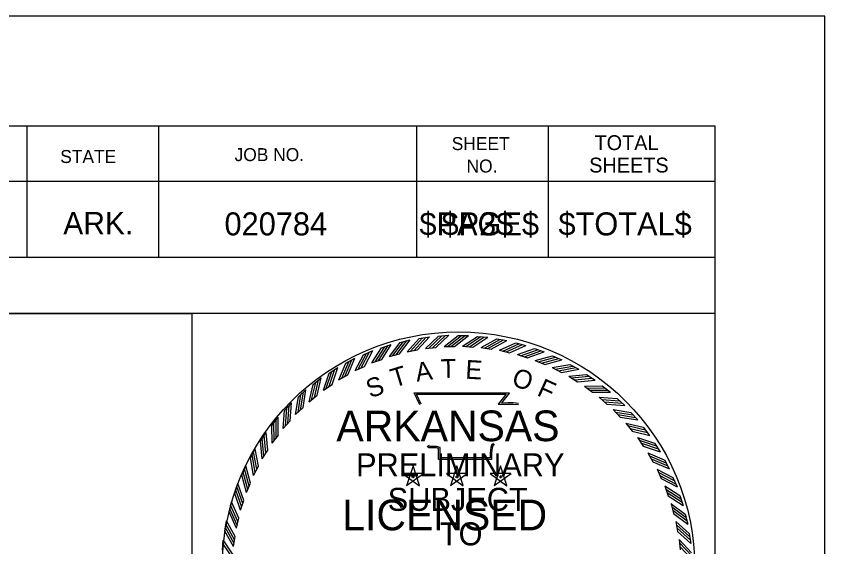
# Model space of a CAD drawing. Extents: x 0 to 1228743, y 0 to 152440.
# Drawn here: x 29.741 to 34, y 19.207 to 22 of the extents above; entities that cross this region are included whole.
import ezdxf

# ---------------------------------------------------------------- set-up
doc = ezdxf.new("R2010")
doc.units = 0
for name, color, linetype in [('R_Border', 7, 'Continuous'), ('R_Draft', 7, 'Continuous'), ('R_No Plot', 7, 'Continuous'), ('R_P1_To_Summary', 7, 'Continuous'), ('R_P2_Summary_To_End_PP', 7, 'Continuous'), ('R_P3_Cross_Sections', 7, 'Continuous'), ('STAMP_JUSTIN', 7, 'Continuous')]:
    doc.layers.add(name, color=color, linetype=linetype)

msp = doc.modelspace()

# ---------------------------------------------------------------- linework, layer by layer
at = {"layer": 'R_Border'}
for p, q in [((1.516, 21.4232), (33.4232, 21.4232)), ((29.7972, 21.4232), (29.7972, 20.7292)), ((30.4912, 21.4232), (30.4912, 20.7292)), ((31.8492, 21.4232), (31.8492, 20.7292)), ((32.5432, 21.4232), (32.5432, 20.7292)), ((33.4232, 0.5768), (33.4232, 21.4232)), ((33.4232, 21.1292), (29.1132, 21.1292)), ((33.4232, 21.1312), (33.4232, 21.1312)), ((33.4232, 20.7292), (29.1132, 20.7292)), ((33.4232, 20.4352), (27.1592, 20.4352))]:
    msp.add_line(p, q, dxfattribs=at)
msp.add_lwpolyline([(34, 22), (0, 22), (0, 0), (34, 0)], close=True, dxfattribs=at)
at = {"layer": 'R_Draft'}
msp.add_circle((32.0709, 19.0937), 1.2447, dxfattribs=at)
at = {"layer": 'R_No Plot'}
for points in [[(33.4232, 17.5816), (33.4232, 10.8708), (1.516, 10.8708), (1.516, 21.4232), (25.1972, 21.4232), (27.1592, 21.4232), (27.1592, 20.4352), (28.7492, 20.4352), (30.6666, 20.4352)], [(30.6666, 20.4352), (30.6666, 17.5816), (33.4232, 17.5816)]]:
    msp.add_lwpolyline(points, dxfattribs=at)
at = {"layer": 'STAMP_JUSTIN'}
for p, q in [((31.9657, 20.3158), (32.0198, 20.3208)), ((32.0686, 20.3188), (32.123, 20.3188)), ((31.7637, 20.2831), (31.8162, 20.297)), ((31.864, 20.3036), (31.9175, 20.3131)), ((32.1704, 20.3148), (32.2246, 20.3108)), ((32.272, 20.3016), (32.3257, 20.2931)), ((32.3721, 20.28), (32.4249, 20.2672)), ((31.5697, 20.2177), (31.6193, 20.2399)), ((31.6653, 20.2544), (31.7166, 20.2725)), ((31.801, 20.2338), (31.8547, 20.2433)), ((31.8972, 20.2514), (31.9514, 20.2564)), ((31.9945, 20.261), (32.0489, 20.261)), ((32.0922, 20.2625), (32.1465, 20.2585)), ((32.1897, 20.256), (32.2435, 20.2475)), ((32.2864, 20.2414), (32.3393, 20.2285)), ((32.4701, 20.2503), (32.5217, 20.2331)), ((31.4775, 20.1731), (31.525, 20.1994)), ((31.6147, 20.1752), (31.6661, 20.1933)), ((31.7067, 20.2084), (31.7593, 20.2222)), ((32.3815, 20.2189), (32.4332, 20.2017)), ((32.4745, 20.1886), (32.5245, 20.1672)), ((32.5654, 20.2126), (32.6153, 20.1912)), ((31.3892, 20.1212), (31.4344, 20.1513)), ((31.5258, 20.1345), (31.5755, 20.1569)), ((32.5646, 20.1507), (32.6127, 20.1252)), ((32.6572, 20.1671), (32.7052, 20.1417)), ((31.4406, 20.0867), (31.4882, 20.113)), ((32.6513, 20.1055), (32.6971, 20.0762)), ((32.7449, 20.1142), (32.7906, 20.0849)), ((31.3056, 20.0621), (31.3481, 20.0958)), ((31.3596, 20.0319), (31.4049, 20.0621)), ((31.2271, 19.9963), (31.2667, 20.0334)), ((32.7339, 20.0534), (32.7772, 20.0203)), ((32.8279, 20.0543), (32.8711, 20.0213)), ((31.2834, 19.9707), (31.3261, 20.0045)), ((32.812, 19.9945), (32.8524, 19.958)), ((32.9058, 19.9877), (32.9461, 19.9513)), ((31.1543, 19.9242), (31.1907, 19.9645)), ((31.2125, 19.9034), (31.2522, 19.9406)), ((32.8849, 19.9294), (32.9222, 19.8897)), ((32.9778, 19.9149), (33.015, 19.8753)), ((31.0877, 19.8464), (31.1206, 19.8896)), ((31.1474, 19.8304), (31.184, 19.8708)), ((32.9522, 19.8586), (32.9861, 19.8159)), ((31.0277, 19.7633), (31.057, 19.8091)), ((33.0436, 19.8364), (33.0774, 19.7938)), ((31.0886, 19.7524), (31.1217, 19.7956)), ((33.0135, 19.7824), (33.0437, 19.7371)), ((30.9748, 19.6756), (31.0003, 19.7236)), ((33.1027, 19.7527), (33.1329, 19.7075)), ((31.0364, 19.6697), (31.0658, 19.7156)), ((33.0682, 19.7014), (33.0946, 19.6537)), ((33.1547, 19.6645), (33.181, 19.6169)), ((30.9294, 19.5838), (30.9507, 19.6338)), ((30.9912, 19.583), (31.0167, 19.6312)), ((31.886, 19.5934), (31.7763, 19.5935)), ((31.7764, 19.5934), (31.865, 19.5288)), ((31.8312, 19.6332), (31.7972, 19.5289)), ((31.7973, 19.529), (31.8861, 19.5934)), ((31.865, 19.529), (31.8312, 19.6333)), ((32.1165, 19.5934), (32.0068, 19.5935)), ((32.0069, 19.5934), (32.0955, 19.5288)), ((32.0617, 19.6332), (32.0277, 19.5289)), ((32.0278, 19.529), (32.1166, 19.5934)), ((32.0955, 19.529), (32.0617, 19.6333)), ((32.3469, 19.5934), (32.2372, 19.5935)), ((32.2373, 19.5934), (32.326, 19.5288)), ((32.2921, 19.6332), (32.2581, 19.5289)), ((32.2583, 19.529), (32.3471, 19.5934)), ((32.326, 19.529), (32.2922, 19.6333)), ((33.1161, 19.6161), (33.1384, 19.5665)), ((31.8234, 19.5759), (31.8397, 19.5759)), ((31.8313, 19.5817), (31.8313, 19.568)), ((32.0538, 19.5759), (32.0701, 19.5759)), ((32.0618, 19.5817), (32.0618, 19.568)), ((32.2843, 19.5759), (32.3006, 19.5759)), ((32.2922, 19.5817), (32.2922, 19.568)), ((33.1992, 19.5722), (33.2215, 19.5227)), ((30.8917, 19.4886), (30.9088, 19.5401)), ((30.9534, 19.4929), (30.9748, 19.543)), ((33.1567, 19.5273), (33.1749, 19.4759)), ((33.236, 19.4766), (33.2541, 19.4254)), ((30.8619, 19.3906), (30.8748, 19.4434)), ((30.9231, 19.4), (30.9403, 19.4516)), ((33.1899, 19.4353), (33.2038, 19.3826)), ((30.8404, 19.2904), (30.8488, 19.3441)), ((30.9006, 19.3048), (30.9135, 19.3578)), ((33.2154, 19.3409), (33.2248, 19.2873)), ((33.2647, 19.3783), (33.2785, 19.3258)), ((30.886, 19.2082), (30.8945, 19.262)), ((33.2852, 19.2779), (33.2946, 19.2244)), ((30.8272, 19.1888), (30.8312, 19.243)), ((33.233, 19.2448), (33.238, 19.1905))]:
    msp.add_line(p, q, dxfattribs=at)
for points in [[(31.9146, 20.2528), (31.9831, 20.3172)], [(31.9333, 20.2549), (32.0018, 20.3193)], [(31.9514, 20.2564), (32.0199, 20.3208)], [(31.9944, 20.261), (32.0685, 20.3188)], [(32.0119, 20.2608), (32.086, 20.3186)], [(32.0308, 20.2612), (32.1049, 20.319)], [(32.0489, 20.261), (32.123, 20.3189)], [(31.7066, 20.2083), (31.7636, 20.2831)], [(31.7236, 20.2126), (31.7805, 20.2874)], [(31.7417, 20.2178), (31.7987, 20.2926)], [(31.7593, 20.2222), (31.8162, 20.297)], [(31.801, 20.2338), (31.8639, 20.3036)], [(31.8182, 20.2366), (31.8812, 20.3065)], [(31.8367, 20.2403), (31.8997, 20.3101)], [(31.8546, 20.2433), (31.9176, 20.3131)], [(31.8971, 20.2514), (31.9656, 20.3157)], [(32.0921, 20.2625), (32.1703, 20.3147)], [(32.1096, 20.261), (32.1877, 20.3133)], [(32.1284, 20.2601), (32.2066, 20.3123)], [(32.1465, 20.2586), (32.2246, 20.3108)], [(32.1897, 20.2559), (32.2719, 20.3015)], [(32.2069, 20.2531), (32.2891, 20.2986)], [(32.2256, 20.2505), (32.3079, 20.2961)], [(32.2435, 20.2476), (32.3257, 20.2931)], [(32.2863, 20.2414), (32.372, 20.28)], [(32.3033, 20.2371), (32.389, 20.2757)], [(31.5588, 20.1496), (31.6027, 20.2327)], [(31.5754, 20.1569), (31.6193, 20.24)], [(31.6147, 20.1751), (31.6653, 20.2543)], [(31.6312, 20.1808), (31.6818, 20.26)], [(31.6489, 20.1875), (31.6995, 20.2667)], [(31.666, 20.1933), (31.7166, 20.2726)], [(32.3217, 20.233), (32.4074, 20.2716)], [(32.3393, 20.2286), (32.425, 20.2672)], [(32.3814, 20.2188), (32.47, 20.2503)], [(32.398, 20.2132), (32.4866, 20.2446)], [(32.416, 20.2076), (32.5046, 20.239)], [(32.4331, 20.2017), (32.5218, 20.2332)], [(31.4722, 20.1044), (31.5091, 20.1909)], [(31.4882, 20.113), (31.525, 20.1995)], [(31.5258, 20.1344), (31.5697, 20.2176)], [(31.5418, 20.1415), (31.5857, 20.2246)], [(32.4744, 20.1886), (32.5653, 20.2126)], [(32.4904, 20.1815), (32.5813, 20.2055)], [(32.5079, 20.1745), (32.5988, 20.1985)], [(32.5245, 20.1672), (32.6154, 20.1912)], [(31.4048, 20.0621), (31.4345, 20.1514)], [(31.4405, 20.0866), (31.4774, 20.1731)], [(31.4559, 20.0949), (31.4928, 20.1814)], [(32.5645, 20.1507), (32.6571, 20.1671)], [(32.5799, 20.1424), (32.6725, 20.1588)], [(32.5968, 20.1339), (32.6893, 20.1503)], [(31.3596, 20.0318), (31.3892, 20.1211)], [(31.3742, 20.0414), (31.4038, 20.1306)], [(31.3897, 20.0522), (31.4193, 20.1415)], [(32.6127, 20.1253), (32.7052, 20.1417)], [(32.6512, 20.1055), (32.7448, 20.1142)], [(32.6658, 20.096), (32.7594, 20.1047)], [(31.2834, 19.9706), (31.3055, 20.062)], [(31.2972, 19.9813), (31.3193, 20.0727)], [(31.3117, 19.9934), (31.3339, 20.0848)], [(31.326, 20.0045), (31.3481, 20.0959)], [(32.6819, 20.0861), (32.7756, 20.0949)], [(32.6971, 20.0762), (32.7907, 20.085)], [(31.2389, 19.9283), (31.2534, 20.0212)], [(31.2522, 19.9406), (31.2667, 20.0335)], [(31.8662, 19.9551), (31.8372, 20.0179), (32.3384, 20.0182), (32.2965, 19.9656), (32.3305, 19.966), (32.359, 19.9664), (32.3874, 19.9633)], [(32.7338, 20.0534), (32.8279, 20.0543)], [(32.7476, 20.0426), (32.8417, 20.0436)], [(32.7629, 20.0315), (32.8569, 20.0324)], [(32.7772, 20.0204), (32.8712, 20.0213)], [(31.2125, 19.9033), (31.227, 19.9962)], [(31.2254, 19.9151), (31.2399, 20.008)], [(31.8734, 19.9585), (31.8496, 20.0099), (32.3219, 20.0102), (32.2798, 19.9574), (32.3306, 19.9581), (32.3586, 19.9584), (32.3865, 19.9554)], [(32.8119, 19.9945), (32.9057, 19.9877)], [(32.8248, 19.9827), (32.9185, 19.9759)], [(31.1593, 19.8432), (31.1661, 19.937)], [(31.1716, 19.8575), (31.1784, 19.9513)], [(31.1839, 19.8708), (31.1907, 19.9646)], [(32.8391, 19.9703), (32.9328, 19.9635)], [(32.8524, 19.9581), (32.9461, 19.9513)], [(31.1474, 19.8303), (31.1542, 19.9241)], [(32.8848, 19.9295), (32.9777, 19.9149)], [(32.8967, 19.9166), (32.9896, 19.9021)], [(32.9099, 19.9031), (33.0028, 19.8886)], [(31.0993, 19.7661), (31.0984, 19.8601)], [(31.1105, 19.7813), (31.1095, 19.8754)], [(31.1216, 19.7956), (31.1206, 19.8896)], [(32.9222, 19.8898), (33.0151, 19.8753)], [(32.9522, 19.8586), (33.0435, 19.8364)], [(31.0657, 19.7155), (31.057, 19.8092)], [(31.0886, 19.7523), (31.0876, 19.8463)], [(32.9629, 19.8448), (33.0543, 19.8226)], [(32.975, 19.8303), (33.0663, 19.8081)], [(32.9861, 19.816), (33.0775, 19.7938)], [(31.0364, 19.6696), (31.0277, 19.7632)], [(31.046, 19.6843), (31.0373, 19.7779)], [(31.0558, 19.7004), (31.0471, 19.794)], [(33.0134, 19.7824), (33.1026, 19.7528)], [(33.023, 19.7678), (33.1122, 19.7381)], [(31.0167, 19.6311), (31.0002, 19.7237)], [(32.2594, 19.7451), (32.2508, 19.7382), (32.248, 19.7278), (32.2452, 19.7018), (32.2452, 19.6672), (31.9654, 19.6672), (31.9654, 19.7139), (31.9654, 19.7243), (31.9541, 19.7278), (31.9143, 19.7278), (31.9072, 19.7386)], [(32.2544, 19.7513), (32.2438, 19.7427), (32.2402, 19.7293), (32.2372, 19.7022), (32.2372, 19.6751), (31.9733, 19.6751), (31.9733, 19.7139), (31.9733, 19.7302), (31.9552, 19.7357), (31.9185, 19.7357), (31.9138, 19.7429)], [(33.0338, 19.7523), (33.123, 19.7227)], [(33.0437, 19.7371), (33.1329, 19.7075)], [(30.9996, 19.5983), (30.9832, 19.6909)], [(31.008, 19.6152), (30.9916, 19.7078)], [(33.0681, 19.7014), (33.1546, 19.6645)], [(33.0765, 19.686), (33.1629, 19.6491)], [(30.9913, 19.5829), (30.9748, 19.6755)], [(33.086, 19.6697), (33.1724, 19.6328)], [(33.0946, 19.6538), (33.1811, 19.6169)], [(30.9604, 19.5088), (30.9364, 19.5997)], [(30.9675, 19.5264), (30.9435, 19.6173)], [(30.9747, 19.5429), (30.9507, 19.6338)], [(33.116, 19.6162), (33.1991, 19.5723)], [(33.123, 19.6002), (33.2062, 19.5563)], [(30.9534, 19.4928), (30.9294, 19.5837)], [(33.1311, 19.5831), (33.2143, 19.5392)], [(33.1384, 19.5665), (33.2216, 19.5226)], [(30.9344, 19.4345), (30.9029, 19.5231)], [(30.9402, 19.4516), (30.9088, 19.5402)], [(33.1567, 19.5273), (33.2359, 19.4767)], [(33.1623, 19.5108), (33.2416, 19.4601)], [(30.9231, 19.3999), (30.8917, 19.4885)], [(30.9288, 19.4164), (30.8974, 19.505)], [(33.169, 19.4931), (33.2483, 19.4425)], [(33.1749, 19.476), (33.2541, 19.4254)], [(30.909, 19.3402), (30.8703, 19.4259)], [(30.9134, 19.3577), (30.8748, 19.4434)], [(33.1898, 19.4354), (33.2646, 19.3784)], [(30.9006, 19.3048), (30.862, 19.3905)], [(30.9049, 19.3217), (30.8663, 19.4074)], [(33.1941, 19.4184), (33.2689, 19.3614)], [(33.1993, 19.4003), (33.2741, 19.3433)], [(33.2038, 19.3827), (33.2786, 19.3257)], [(30.8944, 19.2619), (30.8488, 19.3442)], [(33.2153, 19.341), (33.2851, 19.278)], [(30.8889, 19.2254), (30.8433, 19.3076)], [(30.8914, 19.2441), (30.8458, 19.3263)], [(33.2182, 19.3237), (33.288, 19.2608)], [(33.2219, 19.3052), (33.2917, 19.2422)], [(30.886, 19.2081), (30.8404, 19.2903)], [(33.2249, 19.2874), (33.2947, 19.2244)], [(30.8819, 19.1469), (30.8297, 19.225)], [(30.8834, 19.1649), (30.8312, 19.2431)], [(33.2329, 19.2448), (33.2973, 19.1763)], [(33.2344, 19.2274), (33.2987, 19.1589)], [(33.2365, 19.2086), (33.3009, 19.1401)]]:
    msp.add_lwpolyline(points, dxfattribs=at)

# ---------------------------------------------------------------- texts
at = {"layer": 'R_Border'}
for s, height, p in [('SHEET', 0.0684, (32.035, 21.2952)), ('TOTAL', 0.07819, (32.787, 21.2952)), ('STATE', 0.0684, (29.973, 21.2272)), ('JOB NO.', 0.0684, (30.8913, 21.2372)), ('SHEETS', 0.07819, (32.759, 21.1772)), ('NO.', 0.0684, (32.113, 21.1772)), ('ARK.', 0.11831, (29.9887, 20.8513)), ('020784', 0.1211, (30.8382, 20.8463)), ('$TOTAL$', 0.1211, (32.597, 20.8463))]:
    msp.add_text(s, height=height, dxfattribs=at).set_placement(p)
at = {"layer": 'R_Draft'}
for s, height, p in [('PRELIMINARY', 0.121097, (31.5312, 19.5781)), ('SUBJECT', 0.1211, (31.6976, 19.3964)), ('TO', 0.1211, (31.9722, 19.2148))]:
    msp.add_text(s, height=height, dxfattribs=at).set_placement(p)
at = {"layer": 'R_P1_To_Summary'}
msp.add_text('$PAGE$', height=0.1211, dxfattribs=at).set_placement((31.8646, 20.8463))
at = {"layer": 'R_P2_Summary_To_End_PP'}
msp.add_text('$P2$', height=0.1211, dxfattribs=at).set_placement((31.981, 20.8463))
at = {"layer": 'R_P3_Cross_Sections'}
msp.add_text('$P3$', height=0.1211, dxfattribs=at).set_placement((31.981, 20.8463))
at = {"layer": 'STAMP_JUSTIN'}
for s, rotation, p in [('T', 1.4789, (31.9785, 20.0955)), ('E', 356.672, (32.1051, 20.0925)), ('T', 16.9015, (31.7309, 20.0445)), ('A', 8.6788, (31.8509, 20.0758)), ('O', 341.2218, (32.3451, 20.0586)), ('S', 19.7726, (31.6052, 19.988)), ('F', 335.3628, (32.4783, 20.0065))]:
    msp.add_text(s, height=0.0989, rotation=rotation, dxfattribs=at).set_placement(p)
for s, p in [('ARKANSAS', (31.4275, 19.7632)), ('LICENSED', (31.4583, 19.2942))]:
    msp.add_text(s, height=0.16134, dxfattribs=at).set_placement(p)

doc.saveas('drawing.dxf')
